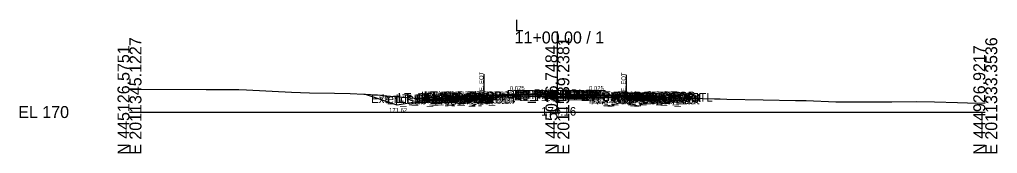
# Model space of a CAD drawing. Extents: x -26 to 4203, y -10 to 9526.
# Drawn here: x -25.7 to 202.8, y 990.3 to 1021.6 of the extents above; entities that cross this region are included whole.
import ezdxf

# ---------------------------------------------------------------- set-up
doc = ezdxf.new("R2010")
doc.units = 0
for name, color, linetype in [('Default', 7, 'Continuous'), ('Exist CMT Pavement', 7, 'Continuous'), ('Exist Cross Section Cell', 7, 'Continuous'), ('Exist XS Center Line Elevation Label', 7, 'Continuous'), ('Exist XS Ground Line', 7, 'Continuous'), ('Prop CMT Pvmt Course 1', 7, 'Continuous'), ('Prop CMT Pvmt Course 1 Wedge', 7, 'Continuous'), ('Prop CMT Pvmt Course 2', 7, 'Continuous'), ('Prop CMT Pvmt Course 2 Wedge', 7, 'Continuous'), ('Prop CMT Pvmt Course 3', 7, 'Continuous'), ('Prop CMT Pvmt Surface', 7, 'Continuous'), ('Prop CMT Pvmt Surface Shoulder', 7, 'Continuous'), ('Prop CMT Pvmt Wedge Surface 1', 7, 'Continuous'), ('Prop CMT Pvmt Wedge Surface 2', 7, 'Continuous'), ('Prop CMT Pvmt Wedge Surface 3', 7, 'Continuous'), ('Prop CMT Shld Paved Course 1', 7, 'Continuous'), ('Prop CMT Shld Paved Course 2', 7, 'Continuous'), ('Prop CMT Shld Paved Course 3', 7, 'Continuous'), ('Prop CMT Slope Grass', 7, 'Continuous'), ('Prop CMT Subgrade Earthwork', 7, 'Continuous'), ('Prop XS Ditch Standard Text', 7, 'Continuous'), ('Prop XS Label Text', 7, 'Continuous'), ('Prop XS SE Text', 7, 'Continuous'), ('Prop XS Side Slope Text', 7, 'Continuous'), ('Scratch_Level_0', 7, 'Continuous')]:
    doc.layers.add(name, color=color, linetype=linetype)

msp = doc.modelspace()

# ---------------------------------------------------------------- linework, layer by layer
at = {"layer": 'Exist CMT Pavement'}
for points in [[(82.83, 1003.87), (82.83, 1003.87), (83.49, 1003.89), (84.16, 1003.9), (84.81, 1003.91), (86.64, 1003.94), (88.8, 1004.03), (89.19, 1004.05), (91.47, 1004.06), (91.7, 1004.06), (91.92, 1004.06), (94.04, 1004.09), (94.17, 1004.09), (95.24, 1004.11), (96.27, 1004.13), (96.71, 1004.13), (96.8, 1004.14), (99.21, 1004.17), (99.45, 1004.17), (100, 1004.16)], [(100, 1004.16), (101.68, 1004.12), (102.08, 1004.11), (104.17, 1004.05), (104.47, 1004.04), (105.13, 1004.03), (106.06, 1004.01), (106.69, 1003.99), (107.4, 1003.98), (109.2, 1003.93), (110.07, 1003.9), (111.7, 1003.85), (113.14, 1003.8), (114.2, 1003.77), (115.02, 1003.74), (116.06, 1003.71), (116.06, 1003.71)]]:
    msp.add_lwpolyline(points, dxfattribs=at)
at = {"layer": 'Exist Cross Section Cell'}
for p, q in [((100, 1000), (100, 1018.85)), ((0, 1000), (100, 1000)), ((100, 1000), (200, 1000))]:
    msp.add_line(p, q, dxfattribs=at)
at = {"layer": 'Exist XS Ground Line'}
msp.add_lwpolyline([(0, 1005.35), (17.93, 1005.28), (18.24, 1005.28), (25.53, 1005.25), (27.38, 1005.2), (37.88, 1004.68), (42.1, 1004.52), (47.9, 1004.43), (51.56, 1004.31), (57.92, 1004.05), (60.08, 1003.81), (70.27, 1002.93), (80.12, 1003.71), (81.44, 1003.81), (81.98, 1003.84), (82.46, 1003.86), (82.83, 1003.87), (83.49, 1003.89), (84.16, 1003.9), (84.81, 1003.91), (86.64, 1003.94), (88.8, 1004.03), (89.19, 1004.05), (91.92, 1004.06), (94.04, 1004.09), (95.24, 1004.11), (96.27, 1004.13), (96.8, 1004.14), (99.45, 1004.17), (100, 1004.16), (101.68, 1004.12), (102.08, 1004.11), (104.47, 1004.04), (105.13, 1004.03), (106.06, 1004.01), (106.69, 1003.99), (107.4, 1003.98), (109.2, 1003.93), (110.07, 1003.9), (111.7, 1003.85), (113.14, 1003.8), (114.2, 1003.77), (115.02, 1003.74), (116.06, 1003.71), (116.72, 1003.68), (118.15, 1003.6), (120.64, 1003.54), (136.71, 1003.11), (138.06, 1003.06), (139.59, 1002.99), (148.08, 1002.82), (155.63, 1002.69), (158.1, 1002.68), (165.09, 1002.4), (168.12, 1002.38), (174.55, 1002.4), (178.14, 1002.42), (184.01, 1002.44), (188.16, 1002.36), (193.48, 1002.26), (198.18, 1002.11), (200, 1002.14)], dxfattribs=at)
at = {"layer": 'Prop CMT Pvmt Course 1'}
for points in [[(100, 1004.32), (81.34, 1003.85)], [(81.34, 1003.85), (81.34, 1003.6)], [(81.34, 1003.6), (81.44, 1003.6)], [(82.83, 1003.76), (100, 1004.19)], [(82.83, 1003.65), (82.83, 1003.77)], [(100, 1004.07), (100, 1004.32)], [(100, 1004.32), (118.17, 1003.86)], [(100, 1004.07), (100, 1004.32)], [(100, 1004.19), (100, 1004.07), (100, 1004.07)], [(118.15, 1003.74), (100, 1004.19)], [(100, 1004.19), (100, 1004.07), (100, 1004.07)], [(116.06, 1003.67), (116.06, 1003.79)], [(118.17, 1003.61), (118.15, 1003.61)], [(118.17, 1003.86), (118.17, 1003.61)]]:
    msp.add_lwpolyline(points, dxfattribs=at)
at = {"layer": 'Prop CMT Pvmt Course 1 Wedge'}
for points in [[(99.28, 1004.17), (99.45, 1004.18)], [(100, 1004.16), (99.45, 1004.17), (99.28, 1004.17)], [(99.45, 1004.18), (100, 1004.19)], [(100, 1004.19), (101.68, 1004.15), (102.08, 1004.14), (104.17, 1004.09), (104.47, 1004.08), (105.13, 1004.06), (106.06, 1004.04), (106.69, 1004.02), (107.4, 1004.01), (109.2, 1003.96), (110.07, 1003.94), (111.7, 1003.9), (113.14, 1003.86), (114.2, 1003.84), (115.02, 1003.82), (116.06, 1003.79), (116.42, 1003.78), (116.72, 1003.77), (117.93, 1003.74), (118.06, 1003.74), (118.15, 1003.74)], [(100, 1004.16), (100, 1004.19)], [(100, 1004.19), (100, 1004.16)], [(118.15, 1003.61), (118.06, 1003.62), (117.93, 1003.62), (117.86, 1003.62), (116.72, 1003.68), (116.42, 1003.69), (116.06, 1003.71), (115.02, 1003.74), (114.2, 1003.77), (113.14, 1003.8), (111.7, 1003.85), (110.07, 1003.9), (109.2, 1003.93), (107.4, 1003.98), (106.69, 1003.99), (106.06, 1004.01), (105.13, 1004.03), (104.47, 1004.04), (104.17, 1004.05), (102.08, 1004.11), (101.68, 1004.12), (100, 1004.16)], [(116.06, 1003.79), (116.06, 1003.67)]]:
    msp.add_lwpolyline(points, dxfattribs=at)
at = {"layer": 'Prop CMT Pvmt Course 2'}
for points in [[(82.83, 1003.63), (81.34, 1003.6)], [(81.34, 1003.6), (81.34, 1003.27)], [(81.34, 1003.27), (82.83, 1003.3)], [(82.83, 1003.31), (82.83, 1003.65)], [(116.06, 1003.33), (116.06, 1003.67)], [(118.15, 1003.61), (118.17, 1003.61)], [(118.17, 1003.28), (118.15, 1003.28)], [(118.17, 1003.61), (118.17, 1003.28)]]:
    msp.add_lwpolyline(points, dxfattribs=at)
at = {"layer": 'Prop CMT Pvmt Course 2 Wedge'}
for points in [[(116.06, 1003.67), (118.06, 1003.62), (118.15, 1003.61)], [(116.06, 1003.67), (116.06, 1003.66)], [(118.15, 1003.6), (118.06, 1003.61), (117.93, 1003.62), (117.86, 1003.62)], [(117.86, 1003.62), (117.93, 1003.62)]]:
    msp.add_lwpolyline(points, dxfattribs=at)
at = {"layer": 'Prop CMT Pvmt Course 3'}
for points in [[(82.83, 1003.3), (81.34, 1003.27)], [(81.34, 1003.27), (81.34, 1002.93)], [(82.83, 1002.98), (82.83, 1003.31)], [(116.06, 1003.33), (118.17, 1003.28)], [(116.06, 1003), (116.06, 1003.33)], [(118.17, 1003.28), (118.17, 1002.95)], [(81.34, 1002.93), (82.83, 1002.98)], [(118.17, 1002.95), (116.06, 1003)]]:
    msp.add_lwpolyline(points, dxfattribs=at)
at = {"layer": 'Prop CMT Pvmt Surface'}
for points in [[(100, 1004.32), (81.34, 1003.85)], [(100, 1004.32), (118.17, 1003.86)]]:
    msp.add_lwpolyline(points, dxfattribs=at)
at = {"layer": 'Prop CMT Pvmt Surface Shoulder'}
for points in [[(81.34, 1003.85), (77.34, 1003.75)], [(118.17, 1003.86), (122.17, 1003.76)]]:
    msp.add_lwpolyline(points, dxfattribs=at)
at = {"layer": 'Prop CMT Pvmt Wedge Surface 1'}
for points in [[(81.34, 1003.6), (81.34, 1003.85)], [(82.83, 1003.63), (81.34, 1003.6)], [(100, 1004.19), (82.83, 1003.76)], [(82.83, 1003.77), (82.83, 1003.65)], [(100, 1004.19), (118.15, 1003.74)], [(116.06, 1003.79), (116.06, 1003.67)], [(118.15, 1003.61), (118.17, 1003.61)], [(118.17, 1003.61), (118.17, 1003.86)]]:
    msp.add_lwpolyline(points, dxfattribs=at)
at = {"layer": 'Prop CMT Pvmt Wedge Surface 2'}
for points in [[(81.34, 1003.6), (81.34, 1003.85)], [(100, 1004.07), (82.83, 1003.64)], [(100, 1004.07), (116.06, 1003.66)], [(118.17, 1003.61), (118.17, 1003.86)]]:
    msp.add_lwpolyline(points, dxfattribs=at)
at = {"layer": 'Prop CMT Pvmt Wedge Surface 3'}
for points in [[(81.34, 1003.27), (81.34, 1003.85)], [(100, 1003.73), (82.83, 1003.3)], [(100, 1003.73), (116.06, 1003.33)], [(118.17, 1003.28), (118.17, 1003.86)]]:
    msp.add_lwpolyline(points, dxfattribs=at)
at = {"layer": 'Prop CMT Shld Paved Course 1'}
for points in [[(81.34, 1003.85), (77.34, 1003.75), (77.08, 1003.49)], [(77.08, 1003.49), (81.34, 1003.6)], [(81.34, 1003.6), (81.34, 1003.85)], [(118.17, 1003.86), (122.17, 1003.76), (122.43, 1003.51)], [(118.17, 1003.61), (118.17, 1003.86)], [(122.43, 1003.51), (118.17, 1003.61)]]:
    msp.add_lwpolyline(points, dxfattribs=at)
at = {"layer": 'Prop CMT Shld Paved Course 2'}
for points in [[(81.34, 1003.6), (77.08, 1003.49), (76.74, 1003.15)], [(76.74, 1003.15), (81.34, 1003.27)], [(81.34, 1003.27), (81.34, 1003.6)], [(118.17, 1003.61), (122.43, 1003.51), (122.77, 1003.16)], [(118.17, 1003.28), (118.17, 1003.61)], [(122.77, 1003.16), (118.17, 1003.28)]]:
    msp.add_lwpolyline(points, dxfattribs=at)
at = {"layer": 'Prop CMT Shld Paved Course 3'}
for points in [[(81.34, 1003.27), (77.24, 1003.16), (76.74, 1003.15), (76.4, 1002.81)], [(81.34, 1002.93), (81.34, 1003.27)], [(118.17, 1003.28), (122.27, 1003.18), (122.77, 1003.16), (123.11, 1002.82)], [(118.17, 1002.95), (118.17, 1003.28)], [(76.4, 1002.81), (81.34, 1002.93)], [(123.11, 1002.82), (118.17, 1002.95)]]:
    msp.add_lwpolyline(points, dxfattribs=at)
at = {"layer": 'Prop CMT Slope Grass'}
for points in [[(62.54, 1001.63), (54.92, 1004.17)], [(77.34, 1003.75), (73.34, 1003.43), (62.54, 1001.63)], [(122.17, 1003.76), (126.17, 1003.39)]]:
    msp.add_lwpolyline(points, dxfattribs=at)
at = {"layer": 'Prop CMT Subgrade Earthwork'}
for points in [[(82.83, 1002.98), (82.83, 1003.87)], [(116.06, 1003), (116.06, 1003.71)], [(123.11, 1002.82), (126.17, 1003.39)], [(75.9, 1002.8), (68.43, 1002.61)], [(81.34, 1002.93), (75.9, 1002.8)], [(82.83, 1002.98), (81.34, 1002.93)], [(116.06, 1003), (118.17, 1002.95)], [(118.17, 1002.95), (123.11, 1002.82)]]:
    msp.add_lwpolyline(points, dxfattribs=at)
at = {"layer": 'Prop XS Label Text'}
for p, q in [((82.83, 1008.87), (82.83, 1003.87)), ((116.06, 1008.71), (116.06, 1003.71))]:
    msp.add_line(p, q, dxfattribs=at)

# ---------------------------------------------------------------- texts
at = {"layer": 'Default'}
msp.add_text('-', height=0.0001, dxfattribs=at).set_placement((0, 1000))
at = {"layer": 'Exist Cross Section Cell'}
for s, p in [('L', (90, 1018.85)), ('11+00.00 / 1', (90, 1016.05)), ('EL 170', (-26, 998.6))]:
    msp.add_text(s, height=2.8, dxfattribs=at).set_placement(p)
for s, p in [('E 2011345.1227', (2.8, 990)), ('E 2011339.2381', (102.8, 990)), ('E 2011333.3536', (202.8, 990)), ('N 445126.5751', (0, 990)), ('N 445026.7484', (100, 990)), ('N 444926.9217', (200, 990))]:
    msp.add_text(s, height=2.8, rotation=90, dxfattribs=at).set_placement(p)
at = {"layer": 'Exist XS Center Line Elevation Label'}
msp.add_text('174.16', height=2, dxfattribs=at).set_placement((96.21, 999.16))
at = {"layer": 'Prop XS Ditch Standard Text'}
msp.add_text('171.62', height=1, dxfattribs=at).set_placement((60.67, 999.93))
at = {"layer": 'Prop XS Label Text'}
for p in [(82.73, 1004.89), (115.96, 1004.73)]:
    msp.add_text('E. EOT', height=1, rotation=90, dxfattribs=at).set_placement(p)
at = {"layer": 'Prop XS SE Text'}
for rotation, p in [(1.4339, (88.91, 1005.04)), (358.5653, (107.38, 1005.13))]:
    msp.add_text('0.025', height=1, rotation=rotation, dxfattribs=at).set_placement(p)
at = {"layer": 'Prop XS Side Slope Text'}
for s, rotation, p in [('3:1', 341.5613, (58.58, 1003.37)), ('6:1', 9.4625, (65.47, 1002.53))]:
    msp.add_text(s, height=1, rotation=rotation, dxfattribs=at).set_placement(p)
at = {"layer": 'Scratch_Level_0'}
for s, p in [('Exterior Boundary', (56.46, 1002.09)), ('LT_Sub_Trench_Out', (60.11, 1001.8)), ('LT_PS3_Shelf_Out', (62.23, 1002.14)), ('LT_GS_OS_CTL', (62.71, 1002.43)), ('LT_Slope_Fill', (62.84, 1002.09)), ('LT_PS3_OEOP', (66.98, 1002.15)), ('LT_PS2_OEOP', (67.32, 1002.49)), ('LT_Sub_OSS_DLT', (67.51, 1002.04)), ('LT_PS1_OEOP', (68.14, 1002.75)), ('LT_Sub Tie Out', (68.78, 1002.81)), ('LT_PV_OEEOP_EG', (68.98, 1002.81)), ('LT_Sub_OEEOP', (70.65, 1001.94)), ('LT_PV2_OEEOP', (70.74, 1002.6)), ('LT_PV3_OEEOP', (70.74, 1002.27)), ('LT_PV1_OEEOP', (71.31, 1002.73)), ('LT_Sub_OEOT', (71.42, 1001.93)), ('LT_PV2_OEOT', (71.52, 1002.6)), ('LT_PV3_OEOT', (71.52, 1002.27)), ('LT_PV1_OEOT', (72.08, 1002.85)), ('RT_PV_IEEOP_EG', (88.14, 1003.16)), ('LT_PV_IEEOP_EG', (88.19, 1003.16)), ('RT_PV2_IEEOP', (89.91, 1003.07)), ('RT_PV3_IEEOP', (89.91, 1002.73)), ('LT_PV2_IEEOP', (89.95, 1003.07)), ('LT_PV3_IEEOP', (89.95, 1002.73)), ('RT_PV1_IEEOP', (90.47, 1003.19)), ('LT_PV1_IEEOP', (90.52, 1003.19)), ('PV2_PGL', (93.91, 1003.07)), ('PV1_PGL', (94.47, 1003.32)), ('RT_Sub Tie Out', (105.44, 1002.6)), ('RT_PV_OEEOP_EG', (105.64, 1002.6)), ('RT_Sub_OSS_DLT', (107.25, 1002.04)), ('RT_Sub_OEEOP', (107.31, 1001.95)), ('RT_PV2_OEEOP', (107.41, 1002.61)), ('RT_PV3_OEEOP', (107.41, 1002.28)), ('RT_Sub_Trench_Out', (107.77, 1001.81)), ('RT_PV1_OEEOP', (107.97, 1002.74)), ('RT_Sub_OEOT', (108.2, 1001.95)), ('RT_PV2_OEOT', (108.29, 1002.61)), ('RT_PV3_OEOT', (108.29, 1002.28)), ('RT_PV1_OEOT', (108.86, 1002.86)), ('RT_PS3_Shelf_Out', (109.21, 1002.15)), ('Exterior Boundary', (110.48, 1002.38)), ('RT_PS2_OEOP', (112.62, 1002.51)), ('RT_PS1_OEOP', (112.93, 1002.76)), ('RT_PS3_OEOP', (112.96, 1002.16)), ('RT_GS_OS_CTL', (115.49, 1002.44)), ('RT_Slope_Cut', (115.93, 1002.38)), ('RT_Slope_Fill', (116.81, 1002.38))]:
    msp.add_text(s, height=2, dxfattribs=at).set_placement(p)

doc.saveas('drawing.dxf')
